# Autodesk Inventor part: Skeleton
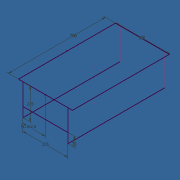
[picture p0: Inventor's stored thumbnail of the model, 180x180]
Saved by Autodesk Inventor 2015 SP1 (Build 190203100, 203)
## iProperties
Category: Mechanical Engineering Drawing and Design - CADD
Manager: Fábio Ricardo de Oliveira Souza
Company: SENAI - Serviço Nacional de Aprendizagem Industrial
Created: 2011-06
Part Number: Skeleton
Material: Steel
Description: Steel - DIN-20CrMoS4
Document SubType Name: Modeling
Designer: Guilherme Augusto Franco de Souza
Engineer: George Geraldo de Oliveia Silva
Authority: Fábio Ricardo de Oliveira Soza
Density: 7.85 g/cm^3
Appearance: Machined 02
Subject: WorldSkill 2011 - London, England
Author: Guilherme Augusto Franco de Souza
Revision Number: 00
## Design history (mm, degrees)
sketch "Sketch2"
  geometry: L1 (-195, 350)-(195, 350); L2 (195, 350)-(195, -350); L3 (195, -350)-(-195, -350); L4 (-195, -350)-(-195, 350); 3 further points
  constraints: 8 end point, 2 midpoint, 2 parallel, 1 horizontal, 1 horizontal alignment, 1 perpendicular, 1 vertical alignment
  dimensions: "d2" = 390 distance of L1.start L1.end; "d3" = 700 distance of L3.end L1.start
workplane "Work Plane3"
sketch "Sketch5"
  geometry: L1 (32.5, 0)-(32.5, -225); L2 (357.5, 0)-(357.5, -225); L3 (357.5, -155)-(32.5, -155); 1 further point
  constraints: 6 end point, 2 horizontal alignment, 2 parallel, 2 point on line, 1 perpendicular, 1 vertical
  dimensions: "d9" = 225 distance of L2.start L2.end; "d10" = 325 distance between parallel lines of L1 L2; "d11" = 162.5 distance from line of point (195, 0) L2 (= 0.5 x d10); "d12" = 70 distance from line of L1.end L3
workplane "Work Plane4"
sketch "Sketch6"
  geometry: L1 (357.5, 0)-(357.5, 225) reference; L2 (32.5, 0)-(32.5, 225) reference; 1 further point
workplane "Work Plane5"
sketch "Sketch7"
  geometry: L1 (325, 0)-(325, 700); L2 (0, 700)-(0, 0); 1 further point
  constraints: 4 end point, 1 parallel, 1 vertical
body "Solid1"
other parameters: "d8" = 0, "d13" = 0
